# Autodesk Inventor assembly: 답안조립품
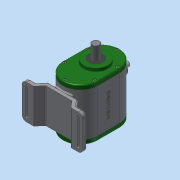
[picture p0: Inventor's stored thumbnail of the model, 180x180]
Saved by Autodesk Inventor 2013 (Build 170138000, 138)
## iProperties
Created: 2018-07
Part Number: 답안조립품
Document SubType Name: Assembly
Designer: dgall
Author: dgall
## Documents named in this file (14)
- C:\Users\dgall\Desktop\380707V1022\답안조립품.iam
- C:\Users\dgall\Desktop\380707V1022\가변스프링.ipt
- C:\Users\dgall\Desktop\380707V1022\뒤커버.ipt
- C:\Users\dgall\Desktop\380707V1022\메인축.ipt
- C:\Users\dgall\Desktop\380707V1022\베어링 608.ipt
- C:\Users\dgall\Desktop\380707V1022\베어링 6003.ipt
- C:\Users\dgall\Desktop\380707V1022\본체.ipt
- C:\Users\dgall\Desktop\380707V1022\볼트 M4.ipt
- C:\Users\dgall\Desktop\380707V1022\부시.ipt
- C:\Users\dgall\Desktop\380707V1022\서브축.ipt
- C:\Users\dgall\Desktop\380707V1022\슬라이더.ipt
- C:\Users\dgall\Desktop\380707V1022\앞커버.ipt
- C:\Users\dgall\Desktop\380707V1022\오일 실 8 22 7.ipt
- C:\Users\dgall\Desktop\380707V1022\오일 실 17 32 8.ipt
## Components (1 placed, 1 different names)
1. 가변스프링:2
